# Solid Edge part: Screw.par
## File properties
Accuracy: 0.99
Title: Screw
Author: Robert a Rhodes jr
Template: Normal.par
Last saved by: CADCIM
Revision: 12
Application: Solid Edge
Material: aluminum
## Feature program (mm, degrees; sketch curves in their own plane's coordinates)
sketch for "unnamed Protrusion 1" plane through (0, 0, 0) normal (0, -1, 0) x-axis (1, 0, 0)
  circle centre (0, 0) radius 12.5
extrude "unnamed Protrusion 1" add finite 25 along +normal
sketch for "ExtrudedProtrusion_2" plane through (0, -25, 0) normal (0, -1, 0) x-axis (1, 0, 0)
  circle centre (0, 0) radius 10
extrude "ExtrudedProtrusion_2" add finite 96 along +normal
sketch for "ExtrudedProtrusion_3" plane through (0, -121, 0) normal (0, -1, 0) x-axis (1, 0, 0)
  circle centre (0, 0) radius 6
extrude "ExtrudedProtrusion_3" add finite 4 along +normal
sketch for "ExtrudedProtrusion_4" plane through (0, -125, 0) normal (0, -1, 0) x-axis (1, 0, 0)
  circle centre (0, 0) radius 4
extrude "ExtrudedProtrusion_4" add finite 6 along +normal
sketch for "unnamed RevolvedProtrusion 1" plane through (0, 0, 0) normal (0, 0, 1) x-axis (1, 0, 0)
  line (0, -131) -> (6, -131)
  line (6, -131) -> (6, -141)
  line (6, -141) -> (0, -143.8522)
  line (0, -143.8522) -> (0, -131)
revolve "unnamed RevolvedProtrusion 1" add full turn 360 deg about sketch line (0, -131) -> (0, -106.3065)
sketch for "ExtrudedCutout_1" plane through (0, 0, 0) normal (1, 0, 0) x-axis (0, 1, 0)
  circle centre (-13, 0) radius 5.5
extrude "ExtrudedCutout_1" cut finite 222.1 symmetric
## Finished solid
Body 1: solid body, 12 faces, 12 edges, 1 vertex.
  Faces by surface: cylinder 6, plane 5, cone 1
  Edges by curve: circle 10, intersection 2
Bounding box of the edges (mm): 25.000 x 141.000 x 25.000, from (-12.5, -141, -12.5) to (12.5, 0, 12.5).
Cylindrical faces by radius (mm): R4 x1, R5.5 x1, R6 x2, R10 x1, R12.5 x1
Conical faces (half-angle, radius in mm at the cone's reference point): 64.5754 deg R6 x1
Planar faces by outward normal: +y 2, -y 3
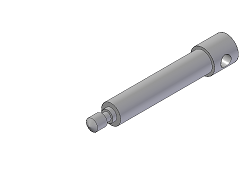
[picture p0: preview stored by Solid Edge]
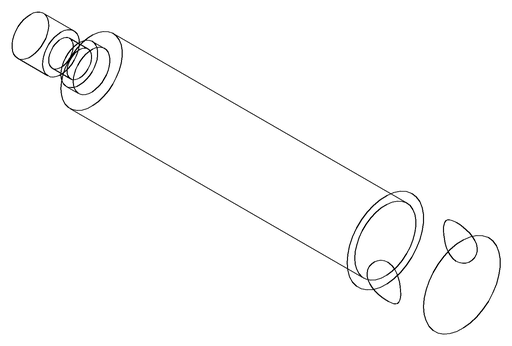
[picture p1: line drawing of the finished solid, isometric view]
